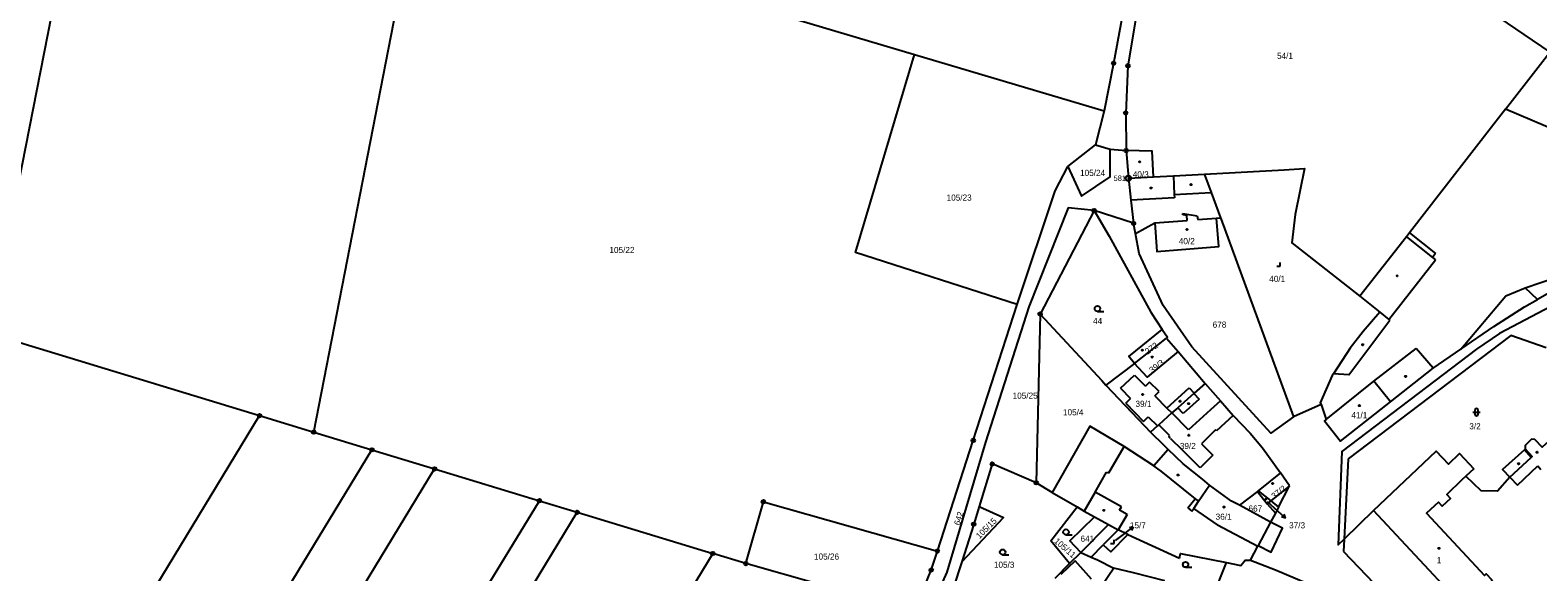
# Model space of a CAD drawing. Extents: x -758582 to -751794, y -998770 to -994350.
# Drawn here: x -754914.8 to -754496.6, y -996760.3 to -996610.1 of the extents above; entities that cross this region are included whole.
import ezdxf

# ---------------------------------------------------------------- set-up
doc = ezdxf.new("R2010")
doc.units = 0
for name, color, linetype in [('Hranice parcel', 7, 'Continuous'), ('Parcelní čísla', 7, 'Continuous'), ('Pop  PČ popisy', 7, 'Continuous'), ('Poz předměty', 7, 'Continuous'), ('Vnitřní kresba', 7, 'Continuous'), ('Značky bodu BP', 7, 'Continuous'), ('Značky budov', 7, 'Continuous'), ('Značky kultur', 7, 'Continuous')]:
    doc.layers.add(name, color=color, linetype=linetype)

msp = doc.modelspace()

# ---------------------------------------------------------------- linework, layer by layer
at = {"layer": 'Hranice parcel'}
for p, q in [((-754836.15, -996721.53), (-754807.71, -996575.72)), ((-754807.71, -996575.72), (-754669.51, -996616.83)), ((-754669.51, -996616.83), (-754616.91, -996632.48)), ((-754505.55, -996631.97), (-754493.24, -996616.16)), ((-754616.91, -996632.48), (-754619.29, -996641.86)), ((-754446.61, -996657.17), (-754505.55, -996631.97)), ((-754626.97, -996647.9), (-754619.29, -996641.86)), ((-754619.29, -996641.86), (-754615.24, -996643.08)), ((-754615.24, -996643.08), (-754610.79, -996643.48)), ((-754610.79, -996643.48), (-754610.18, -996651.15)), ((-754603.21, -996650.76), (-754597.66, -996650.46)), ((-754597.66, -996650.46), (-754589.1, -996649.99)), ((-754610.18, -996651.15), (-754603.21, -996650.76)), ((-754619.68, -996660.1), (-754634.66, -996688.79)), ((-754608.72, -996663.63), (-754619.68, -996660.1)), ((-754608.21, -996666.46), (-754608.72, -996663.63)), ((-754500.14, -996681.53), (-754477.89, -996674.01)), ((-754477.89, -996674.01), (-754496.7, -996684.74)), ((-754496.7, -996684.74), (-754500.14, -996681.53)), ((-754634.66, -996688.79), (-754635.74, -996735.58)), ((-754608.47, -996702.49), (-754599.63, -996695.45)), ((-754599.63, -996695.45), (-754596.37, -996699.21)), ((-754596.37, -996699.21), (-754588.85, -996708.01)), ((-754525.61, -996703.81), (-754517.98, -996698.56)), ((-754608.47, -996702.49), (-754616.38, -996708.47)), ((-754912.07, -996817), (-754851.18, -996716.96)), ((-754851.18, -996716.96), (-754836.15, -996721.53)), ((-754556.74, -996713.87), (-754564.33, -996717.25)), ((-754836.15, -996721.53), (-754820.01, -996726.44)), ((-754881.47, -996827.39), (-754820.01, -996726.44)), ((-754820.01, -996726.44), (-754802.63, -996731.72)), ((-754549.16, -996728.96), (-754550.34, -996751.18)), ((-754864.4, -996833.2), (-754802.63, -996731.72)), ((-754802.63, -996731.72), (-754773.56, -996740.55)), ((-754647.92, -996730.36), (-754651.55, -996742.14)), ((-754635.74, -996735.58), (-754647.92, -996730.36)), ((-754567.98, -996732.82), (-754574.13, -996737.79)), ((-754565.45, -996736.42), (-754567.98, -996732.82)), ((-754516.55, -996733.71), (-754517.71, -996734.79)), ((-754514.37, -996731.68), (-754516.55, -996733.71)), ((-754631.35, -996738.27), (-754635.74, -996735.58)), ((-754631.35, -996738.27), (-754624.41, -996742.27)), ((-754574.39, -996738), (-754579.34, -996741.81)), ((-754574.13, -996737.79), (-754574.39, -996738)), ((-754574.39, -996738), (-754571.63, -996741.39)), ((-754568.52, -996742.3), (-754565.45, -996736.42)), ((-754835.86, -996842.9), (-754773.56, -996740.55)), ((-754773.56, -996740.55), (-754763.03, -996743.75)), ((-754624.41, -996742.27), (-754622.44, -996743.4)), ((-754570.71, -996746.53), (-754579.34, -996741.81)), ((-754571.63, -996741.39), (-754569.4, -996744)), ((-754568.52, -996742.3), (-754569.4, -996744)), ((-754825.52, -996846.41), (-754763.03, -996743.75)), ((-754763.03, -996743.75), (-754725.45, -996755.18)), ((-754622.44, -996743.4), (-754619.58, -996745.03)), ((-754619.58, -996745.03), (-754615.73, -996747.15)), ((-754569.4, -996744), (-754570.71, -996746.53)), ((-754542.19, -996743.28), (-754550.34, -996751.18)), ((-754615.73, -996747.15), (-754623.38, -996754.86)), ((-754613, -996748.65), (-754617.17, -996752.81)), ((-754610.34, -996749.87), (-754613, -996748.65)), ((-754610.34, -996749.87), (-754595.98, -996756.43)), ((-754626.47, -996757.97), (-754623.38, -996754.86)), ((-754623.38, -996754.86), (-754620.53, -996756.16)), ((-754620.53, -996756.16), (-754617.17, -996752.81)), ((-754550.34, -996751.18), (-754550.52, -996754.59)), ((-754725.45, -996755.18), (-754788.01, -996857.97)), ((-754716.28, -996757.97), (-754725.45, -996755.18)), ((-754669.54, -996771.18), (-754716.28, -996757.97)), ((-754656.4, -996757.46), (-754658.75, -996764.81)), ((-754630.49, -996762.03), (-754626.47, -996757.97)), ((-754614.18, -996759.28), (-754621.09, -996769.34)), ((-754620.53, -996756.16), (-754618.77, -996756.96)), ((-754618.77, -996756.96), (-754614.18, -996759.28)), ((-754586.97, -996767.66), (-754583, -996757.68))]:
    msp.add_line(p, q, dxfattribs=at)
for points in [[(-754609.43, -996535.55), (-754569.74, -996564.15), (-754493.24, -996616.16)], [(-754605.55, -996544.6), (-754601.29, -996562.2), (-754602.61, -996574.66), (-754604.74, -996586.83), (-754610.31, -996619.97), (-754610.92, -996633.06), (-754610.79, -996643.48)], [(-754604.88, -996562.82), (-754608.19, -996586.23), (-754614.26, -996619.3), (-754616.91, -996632.48)], [(-754641.05, -996686.13), (-754685.83, -996671.69), (-754669.51, -996616.83)], [(-754505.55, -996631.97), (-754509.42, -996636.95), (-754532.16, -996666.31), (-754533.01, -996667.39), (-754545.98, -996683.8)], [(-754626.97, -996647.9), (-754623.2, -996656.1), (-754615.23, -996650.79), (-754615.24, -996643.08)], [(-754603.21, -996650.76), (-754603.57, -996643.67), (-754610.79, -996643.48)], [(-754641.05, -996686.13), (-754630.46, -996654.59), (-754626.97, -996647.9)], [(-754589.1, -996649.99), (-754566.95, -996648.78), (-754561.32, -996648.45), (-754563.9, -996661.21), (-754564.83, -996669.06), (-754545.98, -996683.8)], [(-754589.1, -996649.99), (-754588.95, -996650.4), (-754587.23, -996655.06), (-754584.62, -996662.16)], [(-754610.18, -996651.15), (-754609.47, -996657.22), (-754608.72, -996663.63)], [(-754619.68, -996660.1), (-754626.86, -996659.32), (-754637.77, -996686.84), (-754649.79, -996724.29), (-754660.56, -996760.31), (-754676.54, -996796.02)], [(-754619.68, -996660.1), (-754615.5, -996667.24), (-754603.94, -996688.23), (-754600.77, -996693.04)], [(-754608.21, -996666.46), (-754602.85, -996663.52), (-754602.24, -996671.43), (-754585.11, -996670.1), (-754585.69, -996662.24), (-754584.62, -996662.16)], [(-754584.62, -996662.16), (-754584.56, -996662.33), (-754564.33, -996717.25)], [(-754564.33, -996717.25), (-754570.66, -996721.84), (-754592.53, -996697.84), (-754600.51, -996686.44), (-754607.21, -996672.05), (-754608.21, -996666.46)], [(-754468.03, -996673.54), (-754507.23, -996694.2), (-754513.57, -996698.51), (-754551, -996726.93), (-754551.94, -996752.73), (-754550.34, -996751.18)], [(-754545.98, -996683.8), (-754540.45, -996688.27), (-754545.07, -996693.66), (-754548.68, -996698.28), (-754553.31, -996705.38), (-754553.68, -996705.85), (-754556.95, -996713.41), (-754556.74, -996713.87)], [(-754517.98, -996698.56), (-754505.46, -996683.73), (-754500.14, -996681.53)], [(-754663.15, -996754.49), (-754653.21, -996723.83), (-754641.05, -996686.13)], [(-754938.81, -996690.33), (-754926.29, -996694.13), (-754851.18, -996716.96)], [(-754634.66, -996688.79), (-754617.51, -996707.25), (-754616.38, -996708.47)], [(-754608.47, -996702.49), (-754610.09, -996700.53), (-754600.77, -996693.04)], [(-754600.77, -996693.04), (-754599.36, -996695.23), (-754599.63, -996695.45)], [(-754494.28, -996698.18), (-754504.12, -996694.74), (-754549.16, -996728.96)], [(-754596.37, -996699.21), (-754605, -996706.26), (-754608.47, -996702.49)], [(-754556.74, -996713.87), (-754555.33, -996718.01), (-754555.8, -996718.39), (-754551.32, -996724.07), (-754537.5, -996713.1), (-754525.61, -996703.81)], [(-754616.38, -996708.47), (-754605.74, -996719.82), (-754604.07, -996721.55)], [(-754588.85, -996708.01), (-754591.91, -996710.74), (-754592.01, -996710.83), (-754596.45, -996714.75), (-754598.12, -996716.22), (-754601.75, -996719.47), (-754602.07, -996719.76), (-754604.07, -996721.55)], [(-754588.85, -996708.01), (-754587.46, -996709.66), (-754584.61, -996712.9), (-754581.07, -996716.91), (-754576.35, -996721.85), (-754572.93, -996725.93), (-754567.98, -996732.82)], [(-754484.63, -996715.85), (-754493.67, -996724.11), (-754495.4, -996725.7), (-754497.42, -996723.56), (-754498.35, -996723.52), (-754500.12, -996725.25), (-754500.11, -996726.17), (-754498.15, -996728.25), (-754498.41, -996728.52), (-754500.26, -996726.41), (-754506.4, -996731.91), (-754504.36, -996734.04)], [(-754599.1, -996726.36), (-754603.08, -996730.88), (-754611.38, -996725.47), (-754620.82, -996719.87), (-754631.35, -996738.27)], [(-754604.07, -996721.55), (-754600.32, -996725.16), (-754599.1, -996726.36)], [(-754579.34, -996741.81), (-754581.54, -996740.64), (-754587.7, -996736.19), (-754589.57, -996734.53), (-754595, -996730.28), (-754599.1, -996726.36)], [(-754542.19, -996743.28), (-754524.83, -996726.78), (-754521.42, -996730.39), (-754518.33, -996727.47), (-754514.37, -996731.68)], [(-754504.36, -996734.04), (-754507.8, -996737.87), (-754512.34, -996737.79), (-754516.55, -996733.71)], [(-754574.13, -996737.79), (-754570.64, -996740.59), (-754568.52, -996742.3)], [(-754517.71, -996734.79), (-754521.88, -996738.79), (-754520.85, -996739.93), (-754523.11, -996742.06), (-754524.18, -996740.92), (-754527.46, -996744.01), (-754511.37, -996761.27), (-754510.88, -996760.84), (-754509.34, -996762.49), (-754509.43, -996762.58), (-754507.38, -996764.77), (-754507.28, -996764.69), (-754505.78, -996766.3), (-754506.25, -996766.72), (-754504.11, -996769.04), (-754503.6, -996768.55), (-754490.16, -996782.99), (-754490.7, -996783.49), (-754488.08, -996786.29), (-754495.35, -996793.06)], [(-754716.28, -996757.97), (-754711.43, -996740.84), (-754663.15, -996754.49)], [(-754651.55, -996742.14), (-754644.84, -996745.18), (-754656.4, -996757.46)], [(-754651.55, -996742.14), (-754653.06, -996747.04), (-754656.4, -996757.46)], [(-754626.47, -996757.97), (-754631.64, -996751.64), (-754624.41, -996742.27)], [(-754623.38, -996754.86), (-754626.43, -996751.64), (-754619.58, -996745.03)], [(-754576.26, -996757.01), (-754574.28, -996753.17), (-754574.15, -996752.93), (-754570.6, -996754.78), (-754567.43, -996748.16), (-754570.71, -996746.53)], [(-754498.09, -996790.19), (-754513.58, -996773.76), (-754514.01, -996774.11), (-754519.03, -996768.77), (-754518.65, -996768.41), (-754519.06, -996767.99), (-754542.19, -996743.28)], [(-754617.17, -996752.81), (-754615.02, -996754.73), (-754610.34, -996749.87)], [(-754669.54, -996771.18), (-754664.86, -996759.76), (-754663.15, -996754.49)], [(-754550.52, -996754.59), (-754510.63, -996796.17), (-754504.74, -996796.25), (-754498.09, -996790.19)], [(-754600.1, -996762.77), (-754608.76, -996760.51), (-754614.18, -996759.28)], [(-754595.98, -996756.43), (-754595.68, -996755.17), (-754583, -996757.68)], [(-754583, -996757.68), (-754579.02, -996758.47), (-754577.76, -996757.07), (-754576.26, -996757.01)], [(-754576.26, -996757.01), (-754569.4, -996759.74), (-754557.83, -996764.59), (-754557.59, -996765.06), (-754561.98, -996775.61), (-754564.36, -996774.79), (-754565.63, -996777.81), (-754566.31, -996779.33)]]:
    msp.add_lwpolyline(points, dxfattribs=at)
at = {"layer": 'Pop  PČ popisy'}
for p, q in [((-754571.7, -996740.74), (-754568.81, -996743.34)), ((-754568.81, -996743.34), (-754566.58, -996745.35)), ((-754566.58, -996745.35), (-754567.66, -996745.05)), ((-754566.58, -996745.35), (-754566.99, -996744.31)), ((-754613.71, -996751.55), (-754611.2, -996749.64)), ((-754611.2, -996749.64), (-754608.8, -996747.83)), ((-754608.8, -996747.83), (-754609.9, -996748.04)), ((-754608.8, -996747.83), (-754609.3, -996748.84))]:
    msp.add_line(p, q, dxfattribs=at)
at = {"layer": 'Poz předměty'}
msp.add_line((-754906.99, -996596.3), (-754926.29, -996694.13), dxfattribs=at)
at = {"layer": 'Vnitřní kresba'}
for p, q in [((-754597.66, -996650.46), (-754597.43, -996655.63)), ((-754597.39, -996656.54), (-754609.47, -996657.22)), ((-754597.43, -996655.63), (-754587.23, -996655.06)), ((-754597.43, -996655.63), (-754597.39, -996656.54)), ((-754602.85, -996663.52), (-754593.82, -996662.87)), ((-754595.11, -996661.3), (-754595.05, -996660.94)), ((-754593.92, -996661.5), (-754595.11, -996661.3)), ((-754595.05, -996660.94), (-754591.07, -996661.59)), ((-754593.82, -996662.87), (-754593.92, -996661.5)), ((-754591.07, -996661.59), (-754590.89, -996662.62)), ((-754590.89, -996662.62), (-754585.69, -996662.24)), ((-754532.16, -996666.31), (-754524.97, -996671.98)), ((-754533.01, -996667.39), (-754525.8, -996673.09)), ((-754537.88, -996690.3), (-754524.98, -996673.74)), ((-754524.97, -996671.98), (-754525.8, -996673.09)), ((-754525.8, -996673.09), (-754524.98, -996673.74)), ((-754508.78, -996692.24), (-754500.3, -996686.8)), ((-754500.3, -996686.8), (-754496.7, -996684.74)), ((-754549.01, -996705.64), (-754537.65, -996690.49)), ((-754540.45, -996688.27), (-754537.88, -996690.3)), ((-754537.88, -996690.3), (-754537.65, -996690.49)), ((-754517.98, -996698.56), (-754508.78, -996692.24)), ((-754542.12, -996707.42), (-754530.36, -996698.37)), ((-754525.61, -996703.81), (-754530.36, -996698.37)), ((-754612.34, -996709.33), (-754608.44, -996705.74)), ((-754608.44, -996705.74), (-754605.4, -996708.8)), ((-754604.32, -996707.69), (-754605.4, -996708.8)), ((-754601.62, -996710.31), (-754604.32, -996707.69)), ((-754555.33, -996718.01), (-754542.12, -996707.42)), ((-754549.01, -996705.64), (-754553.31, -996705.38)), ((-754537.5, -996713.1), (-754542.12, -996707.42)), ((-754612.34, -996709.33), (-754609.55, -996712.23)), ((-754610.86, -996713.48), (-754609.55, -996712.23)), ((-754602.83, -996711.43), (-754601.62, -996710.31)), ((-754602.83, -996711.43), (-754599.52, -996714.86)), ((-754599.52, -996714.86), (-754593.27, -996709.21)), ((-754590.56, -996712.41), (-754595, -996716.36)), ((-754593.27, -996709.21), (-754591.91, -996710.74)), ((-754592.01, -996710.83), (-754590.56, -996712.41)), ((-754584.61, -996712.9), (-754587.4, -996715.36)), ((-754610.86, -996713.48), (-754605.95, -996718.56)), ((-754605.95, -996718.56), (-754604.66, -996717.31)), ((-754604.66, -996717.31), (-754602.07, -996719.76)), ((-754599.52, -996714.86), (-754598.12, -996716.22)), ((-754593.49, -996720.86), (-754598.12, -996716.22)), ((-754595, -996716.36), (-754596.45, -996714.75)), ((-754587.4, -996715.36), (-754593.49, -996720.86)), ((-754581.07, -996716.91), (-754585.77, -996721.15)), ((-754598.72, -996722.46), (-754601.75, -996719.47)), ((-754586, -996720.89), (-754589.88, -996724.79)), ((-754585.77, -996721.15), (-754586, -996720.89)), ((-754615.55, -996732.81), (-754611.38, -996725.47)), ((-754598.87, -996722.95), (-754598.72, -996722.46)), ((-754598.5, -996723.31), (-754598.87, -996722.95)), ((-754598.5, -996723.31), (-754595.28, -996726.46)), ((-754589.88, -996724.79), (-754586.73, -996727.89)), ((-754590.25, -996731.4), (-754595.28, -996726.46)), ((-754586.73, -996727.89), (-754590.25, -996731.4)), ((-754504.36, -996734.04), (-754498.41, -996728.52)), ((-754619.41, -996738.15), (-754616.22, -996732.61)), ((-754616.22, -996732.61), (-754615.55, -996732.81)), ((-754601.66, -996732.02), (-754603.08, -996730.88)), ((-754601.66, -996732.02), (-754591.67, -996740.01)), ((-754504.36, -996734.04), (-754502.25, -996736.24)), ((-754502.25, -996736.24), (-754496.62, -996730.91)), ((-754496.62, -996730.91), (-754495.75, -996731.89)), ((-754619.41, -996738.15), (-754622.44, -996743.4)), ((-754612.11, -996742.22), (-754619.41, -996738.15)), ((-754590.72, -996740.7), (-754587.7, -996736.19)), ((-754565.45, -996736.42), (-754570.64, -996740.59)), ((-754612.65, -996743.15), (-754612.11, -996742.22)), ((-754593.69, -996742.55), (-754591.67, -996740.01)), ((-754593.69, -996742.55), (-754592.59, -996743.41)), ((-754592.06, -996742.67), (-754590.72, -996740.7)), ((-754591.67, -996740.01), (-754590.72, -996740.7)), ((-754570.64, -996740.59), (-754571.63, -996741.39)), ((-754610.55, -996744.37), (-754613, -996748.65)), ((-754610.55, -996744.37), (-754612.65, -996743.15)), ((-754592.59, -996743.41), (-754592.06, -996742.67)), ((-754585.43, -996747.27), (-754592.06, -996742.67)), ((-754570.71, -996746.53), (-754574.15, -996752.93)), ((-754615.73, -996747.15), (-754613, -996748.65)), ((-754585.43, -996747.27), (-754574.28, -996753.17)), ((-754624.94, -996757.21), (-754628.9, -996760.99)), ((-754620.36, -996762.25), (-754624.94, -996757.21))]:
    msp.add_line(p, q, dxfattribs=at)
at = {"layer": 'Značky bodu BP'}
for centre, radius in [((-754614.26, -996619.3), 0.5), ((-754614.26, -996619.3), 0.0303), ((-754610.31, -996619.97), 0.5), ((-754610.31, -996619.97), 0.0303), ((-754610.92, -996633.06), 0.5), ((-754610.92, -996633.06), 0.0303), ((-754610.79, -996643.48), 0.5), ((-754610.79, -996643.48), 0.0303), ((-754610.18, -996651.14), 0.75), ((-754610.18, -996651.14), 0.03), ((-754619.68, -996660.1), 0.5), ((-754619.68, -996660.1), 0.0303), ((-754608.72, -996663.63), 0.5), ((-754608.72, -996663.63), 0.0303), ((-754634.66, -996688.79), 0.5), ((-754634.66, -996688.79), 0.0303), ((-754851.18, -996716.96), 0.5), ((-754851.18, -996716.96), 0.0303), ((-754836.15, -996721.53), 0.5), ((-754836.15, -996721.53), 0.0303), ((-754653.21, -996723.83), 0.5), ((-754653.21, -996723.83), 0.0303), ((-754820.01, -996726.44), 0.5), ((-754820.01, -996726.44), 0.0303), ((-754647.92, -996730.36), 0.5), ((-754802.63, -996731.72), 0.5), ((-754802.63, -996731.72), 0.0303), ((-754647.92, -996730.36), 0.0303), ((-754635.74, -996735.58), 0.5), ((-754635.74, -996735.58), 0.0303), ((-754773.56, -996740.55), 0.5), ((-754773.56, -996740.55), 0.0303), ((-754711.43, -996740.84), 0.5), ((-754711.43, -996740.84), 0.0303), ((-754763.03, -996743.75), 0.5), ((-754763.03, -996743.75), 0.0303), ((-754653.06, -996747.04), 0.5), ((-754653.06, -996747.04), 0.0303), ((-754725.45, -996755.18), 0.5), ((-754663.15, -996754.49), 0.5), ((-754663.15, -996754.49), 0.0303), ((-754725.45, -996755.18), 0.0303), ((-754716.28, -996757.97), 0.5), ((-754716.28, -996757.97), 0.0303), ((-754664.86, -996759.76), 0.5), ((-754664.86, -996759.76), 0.0303)]:
    msp.add_circle(centre, radius, dxfattribs=at)
at = {"layer": 'Značky budov'}
for centre in [(-754607.02, -996646.59), (-754603.87, -996653.86), (-754592.8, -996652.9), (-754593.93, -996665.36), (-754535.62, -996678.19), (-754606.31, -996698.82), (-754603.56, -996700.73), (-754545.17, -996697.3), (-754533.27, -996706.08), (-754606.22, -996711.1), (-754595.85, -996712.97), (-754593.46, -996713.64), (-754546.08, -996714.18), (-754593.39, -996722.4), (-754496.8, -996727.11), (-754596.39, -996733.41), (-754501.94, -996730.29), (-754570.17, -996735.78), (-754583.65, -996742.3), (-754572.05, -996740.11), (-754616.98, -996743.22), (-754524.02, -996753.75)]:
    msp.add_circle(centre, 0.175, dxfattribs=at)
at = {"layer": 'Značky kultur'}
for p, q in [((-754569.03, -996675.51), (-754568.03, -996675.51)), ((-754568.03, -996675.51), (-754568.03, -996674.51)), ((-754618.75, -996688.05), (-754617, -996688.05)), ((-754514.6, -996716.01), (-754512.6, -996716.01)), ((-754514.1, -996715.51), (-754514.1, -996716.51)), ((-754513.1, -996716.51), (-754513.1, -996715.51)), ((-754627.48, -996749.97), (-754625.73, -996749.97)), ((-754615.16, -996752.4), (-754614.16, -996752.4)), ((-754614.16, -996752.4), (-754614.16, -996751.4)), ((-754645.05, -996755.53), (-754643.3, -996755.53)), ((-754594.32, -996758.99), (-754592.57, -996758.99))]:
    msp.add_line(p, q, dxfattribs=at)
for centre in [(-754618.75, -996687.3), (-754627.48, -996749.22), (-754645.05, -996754.78), (-754594.32, -996758.24)]:
    msp.add_circle(centre, 0.75, dxfattribs=at)
for centre, start, end in [((-754513.6, -996715.51), 0, 180), ((-754513.6, -996716.51), 180, 359.9879)]:
    msp.add_arc(centre, 0.5, start, end, dxfattribs=at)

# ---------------------------------------------------------------- texts
at = {"layer": 'Parcelní čísla'}
for s, p in [('54/1', (-754568.94, -996618.06)), ('105/24', (-754623.57, -996650.51)), ('40/3', (-754608.95, -996650.92)), ('105/23', (-754660.59, -996657.36)), ('105/22', (-754754.12, -996671.88)), ('40/2', (-754596.18, -996669.43)), ('40/1', (-754571.1, -996679.89)), ('44', (-754619.96, -996691.56)), ('678', (-754586.79, -996692.57)), ('105/25', (-754642.28, -996712.27)), ('39/1', (-754608.2, -996714.52)), ('105/4', (-754628.31, -996716.88)), ('41/1', (-754548.33, -996717.69)), ('3/2', (-754515.6, -996720.75)), ('39/2', (-754595.9, -996726.22)), ('667', (-754576.85, -996743.56)), ('15/7', (-754609.75, -996748.21)), ('36/1', (-754585.97, -996745.83)), ('37/3', (-754565.58, -996748.2)), ('641', (-754623.44, -996751.91)), ('105/26', (-754697.38, -996756.88)), ('105/3', (-754647.48, -996759.15)), ('1', (-754524.63, -996757.88))]:
    msp.add_text(s, height=1.7, dxfattribs=at).set_placement(p)
for s, rotation, p in [('272', 36, (-754604.81, -996700.09)), ('39/3', 37, (-754603.6, -996705.27)), ('37/2', 38, (-754569.7, -996740.19)), ('642', 73, (-754656.97, -996747.51)), ('105/15', 45, (-754651.44, -996751.23)), ('105/11', 319, (-754630.91, -996751.99))]:
    msp.add_text(s, height=1.7, rotation=rotation, dxfattribs=at).set_placement(p)
at = {"layer": 'Značky bodu BP'}
msp.add_text('581', height=1.5, dxfattribs=at).set_placement((-754614.28, -996651.89))

doc.saveas('drawing.dxf')
